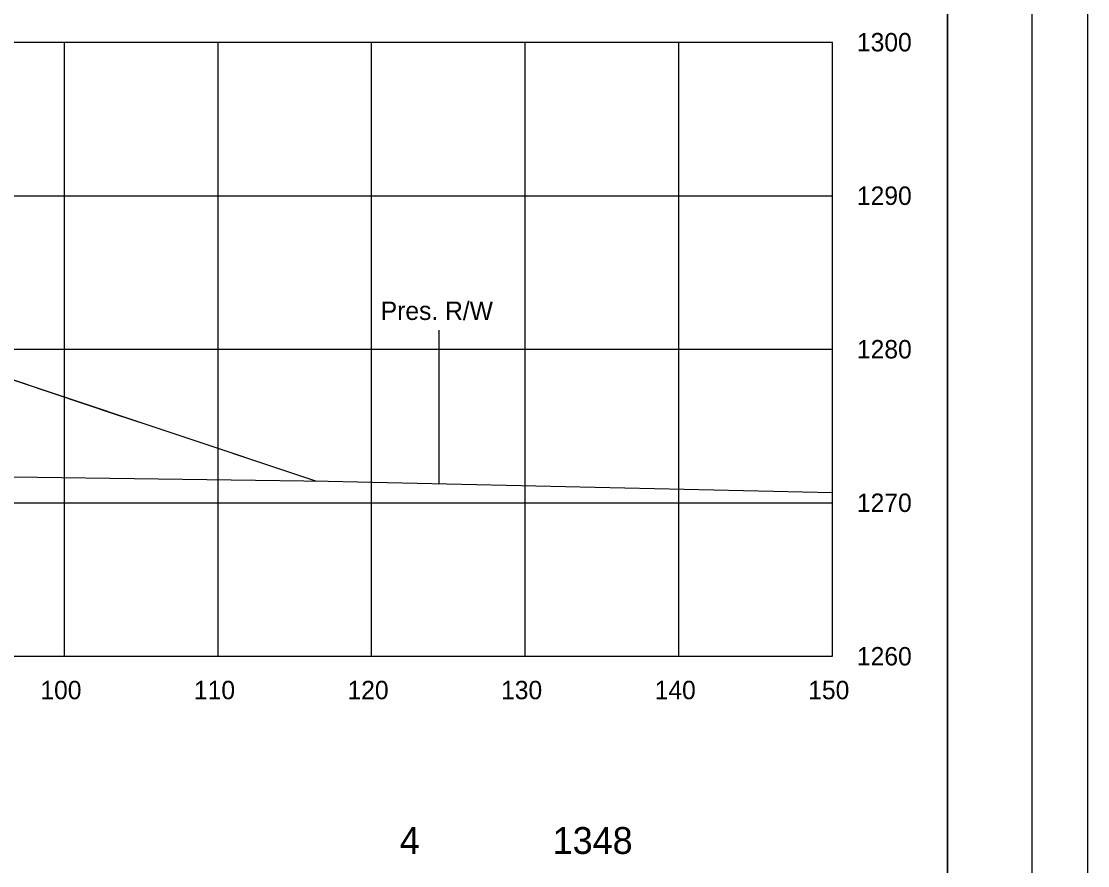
# Model space of a CAD drawing. Extents: x 2148105 to 2149976, y 144169 to 149705.
# Drawn here: x 2148510.5 to 2148579.9, y 146243.3 to 146298.3 of the extents above; entities that cross this region are included whole.
import ezdxf

# ---------------------------------------------------------------- set-up
doc = ezdxf.new("R2010")
doc.units = 0
for name, color, linetype in [('PH1a-PR-ServRd', 7, 'Continuous'), ('PR-ApproachSlab', 7, 'Continuous'), ('PR-SHLDR-RMP-H', 7, 'Continuous'), ('PR_Align_Ramp_A', 7, 'Continuous'), ('PR_Align_Ramp_E', 7, 'Continuous'), ('PR_Align_Ramp_J', 7, 'Continuous'), ('PR_Storm_Conc_Box_PH1B', 7, 'Continuous'), ('PR_Storm_Conc_Pipe_PH1B', 7, 'Continuous'), ('PR_Storm_Inlet_CICI_PH1B', 7, 'Continuous'), ('PR_Storm_MH_PH1A', 7, 'Continuous'), ('PR_Storm_MH_PH1B', 7, 'Continuous'), ('PR_Storm_Standard_Median_Drain_PH1B', 7, 'Continuous')]:
    doc.layers.add(name, color=color, linetype=linetype)

msp = doc.modelspace()

# ---------------------------------------------------------------- linework, layer by layer
at = {"layer": 'PH1a-PR-ServRd'}
msp.add_lwpolyline([(2148570.822, 146121.906), (2148255.822, 146121.906), (2148255.822, 146331.906), (2148570.822, 146331.906)], close=True, dxfattribs=at)
at = {"layer": 'PR-ApproachSlab'}
msp.add_lwpolyline([(2148508.34, 146275.447), (2148516.627, 146272.685), (2148518.686, 146271.999), (2148520.366, 146271.438), (2148529.72, 146268.321)], dxfattribs=at)
at = {"layer": 'PR-SHLDR-RMP-H'}
msp.add_lwpolyline([(2148508.34, 146275.447), (2148518.686, 146271.999), (2148529.72, 146268.321)], dxfattribs=at)
at = {"layer": 'PR_Align_Ramp_E'}
msp.add_lwpolyline([(2148219.947, 146345.156), (2148579.947, 146345.156), (2148579.947, 146105.156), (2148219.947, 146105.156)], close=True, dxfattribs=at)
at = {"layer": 'PR_Align_Ramp_J'}
msp.add_lwpolyline([(2148236.322, 146336.906), (2148576.322, 146336.906), (2148576.322, 146116.906), (2148236.322, 146116.906)], close=True, dxfattribs=at)
at = {"layer": 'PR_Storm_Conc_Box_PH1B'}
for p, q in [((2148263.322, 146296.906), (2148563.322, 146296.906)), ((2148513.322, 146256.906), (2148513.322, 146296.906)), ((2148523.322, 146256.906), (2148523.322, 146296.906)), ((2148533.322, 146256.906), (2148533.322, 146296.906)), ((2148543.322, 146256.906), (2148543.322, 146296.906)), ((2148553.322, 146256.906), (2148553.322, 146296.906)), ((2148563.322, 146256.906), (2148563.322, 146296.906)), ((2148263.322, 146286.906), (2148563.322, 146286.906)), ((2148263.322, 146276.906), (2148563.322, 146276.906)), ((2148263.322, 146266.906), (2148563.322, 146266.906)), ((2148263.322, 146256.906), (2148563.322, 146256.906))]:
    msp.add_line(p, q, dxfattribs=at)
at = {"layer": 'PR_Storm_Conc_Pipe_PH1B'}
msp.add_lwpolyline([(2148255.822, 146121.906), (2148570.822, 146121.906), (2148570.822, 146331.906), (2148255.822, 146331.906)], close=True, dxfattribs=at)
msp.add_lwpolyline([(2148255.822, 146121.906), (2148570.822, 146121.906), (2148570.822, 146331.906), (2148255.822, 146331.906)], close=True, dxfattribs=at)
at = {"layer": 'PR_Storm_Inlet_CICI_PH1B'}
msp.add_lwpolyline([(2148263.322, 146271.831), (2148272.969, 146271.838), (2148293.81, 146271.592), (2148299.454, 146271.584), (2148318.245, 146271.455), (2148331.16, 146271.358), (2148354.889, 146271.105), (2148376.229, 146270.718), (2148379.968, 146270.626), (2148401.31, 146270.143), (2148417.186, 146269.837), (2148433.501, 146269.537), (2148471.077, 146269.058), (2148505.194, 146268.668), (2148530.488, 146268.31), (2148563.322, 146267.566)], dxfattribs=at)
at = {"layer": 'PR_Storm_MH_PH1A'}
msp.add_line((2148537.712, 146268.146), (2148537.712, 146278.146), dxfattribs=at)
at = {"layer": 'PR_Storm_Standard_Median_Drain_PH1B'}
for p, q in [((2148563.322, 146256.906), (2148563.322, 146296.906)), ((2148263.322, 146256.906), (2148563.322, 146256.906))]:
    msp.add_line(p, q, dxfattribs=at)

# ---------------------------------------------------------------- texts
at = {"layer": 'PR_Align_Ramp_A'}
for s, p in [('4', (2148535.151, 146244.031)), ('1348', (2148545.111, 146244.031))]:
    msp.add_text(s, height=1.75, dxfattribs=at).set_placement(p)
at = {"layer": 'PR_Storm_MH_PH1A'}
msp.add_text('Pres. R/W', height=1.2, rotation=360, dxfattribs=at).set_placement((2148533.912, 146278.813))
at = {"layer": 'PR_Storm_MH_PH1B'}
for s, p in [('1300', (2148564.922, 146296.306)), ('1290', (2148564.922, 146286.306)), ('1280', (2148564.922, 146276.306)), ('1270', (2148564.922, 146266.306)), ('1260', (2148564.922, 146256.306)), ('100', (2148511.749, 146254.106)), ('110', (2148521.749, 146254.106)), ('120', (2148531.749, 146254.106)), ('130', (2148541.749, 146254.106)), ('140', (2148551.749, 146254.106)), ('150', (2148561.749, 146254.106))]:
    msp.add_text(s, height=1.2, dxfattribs=at).set_placement(p)

doc.saveas('drawing.dxf')
